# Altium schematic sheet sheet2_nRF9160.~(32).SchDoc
size A3; SheetNumber: 2; SheetTotal: 3
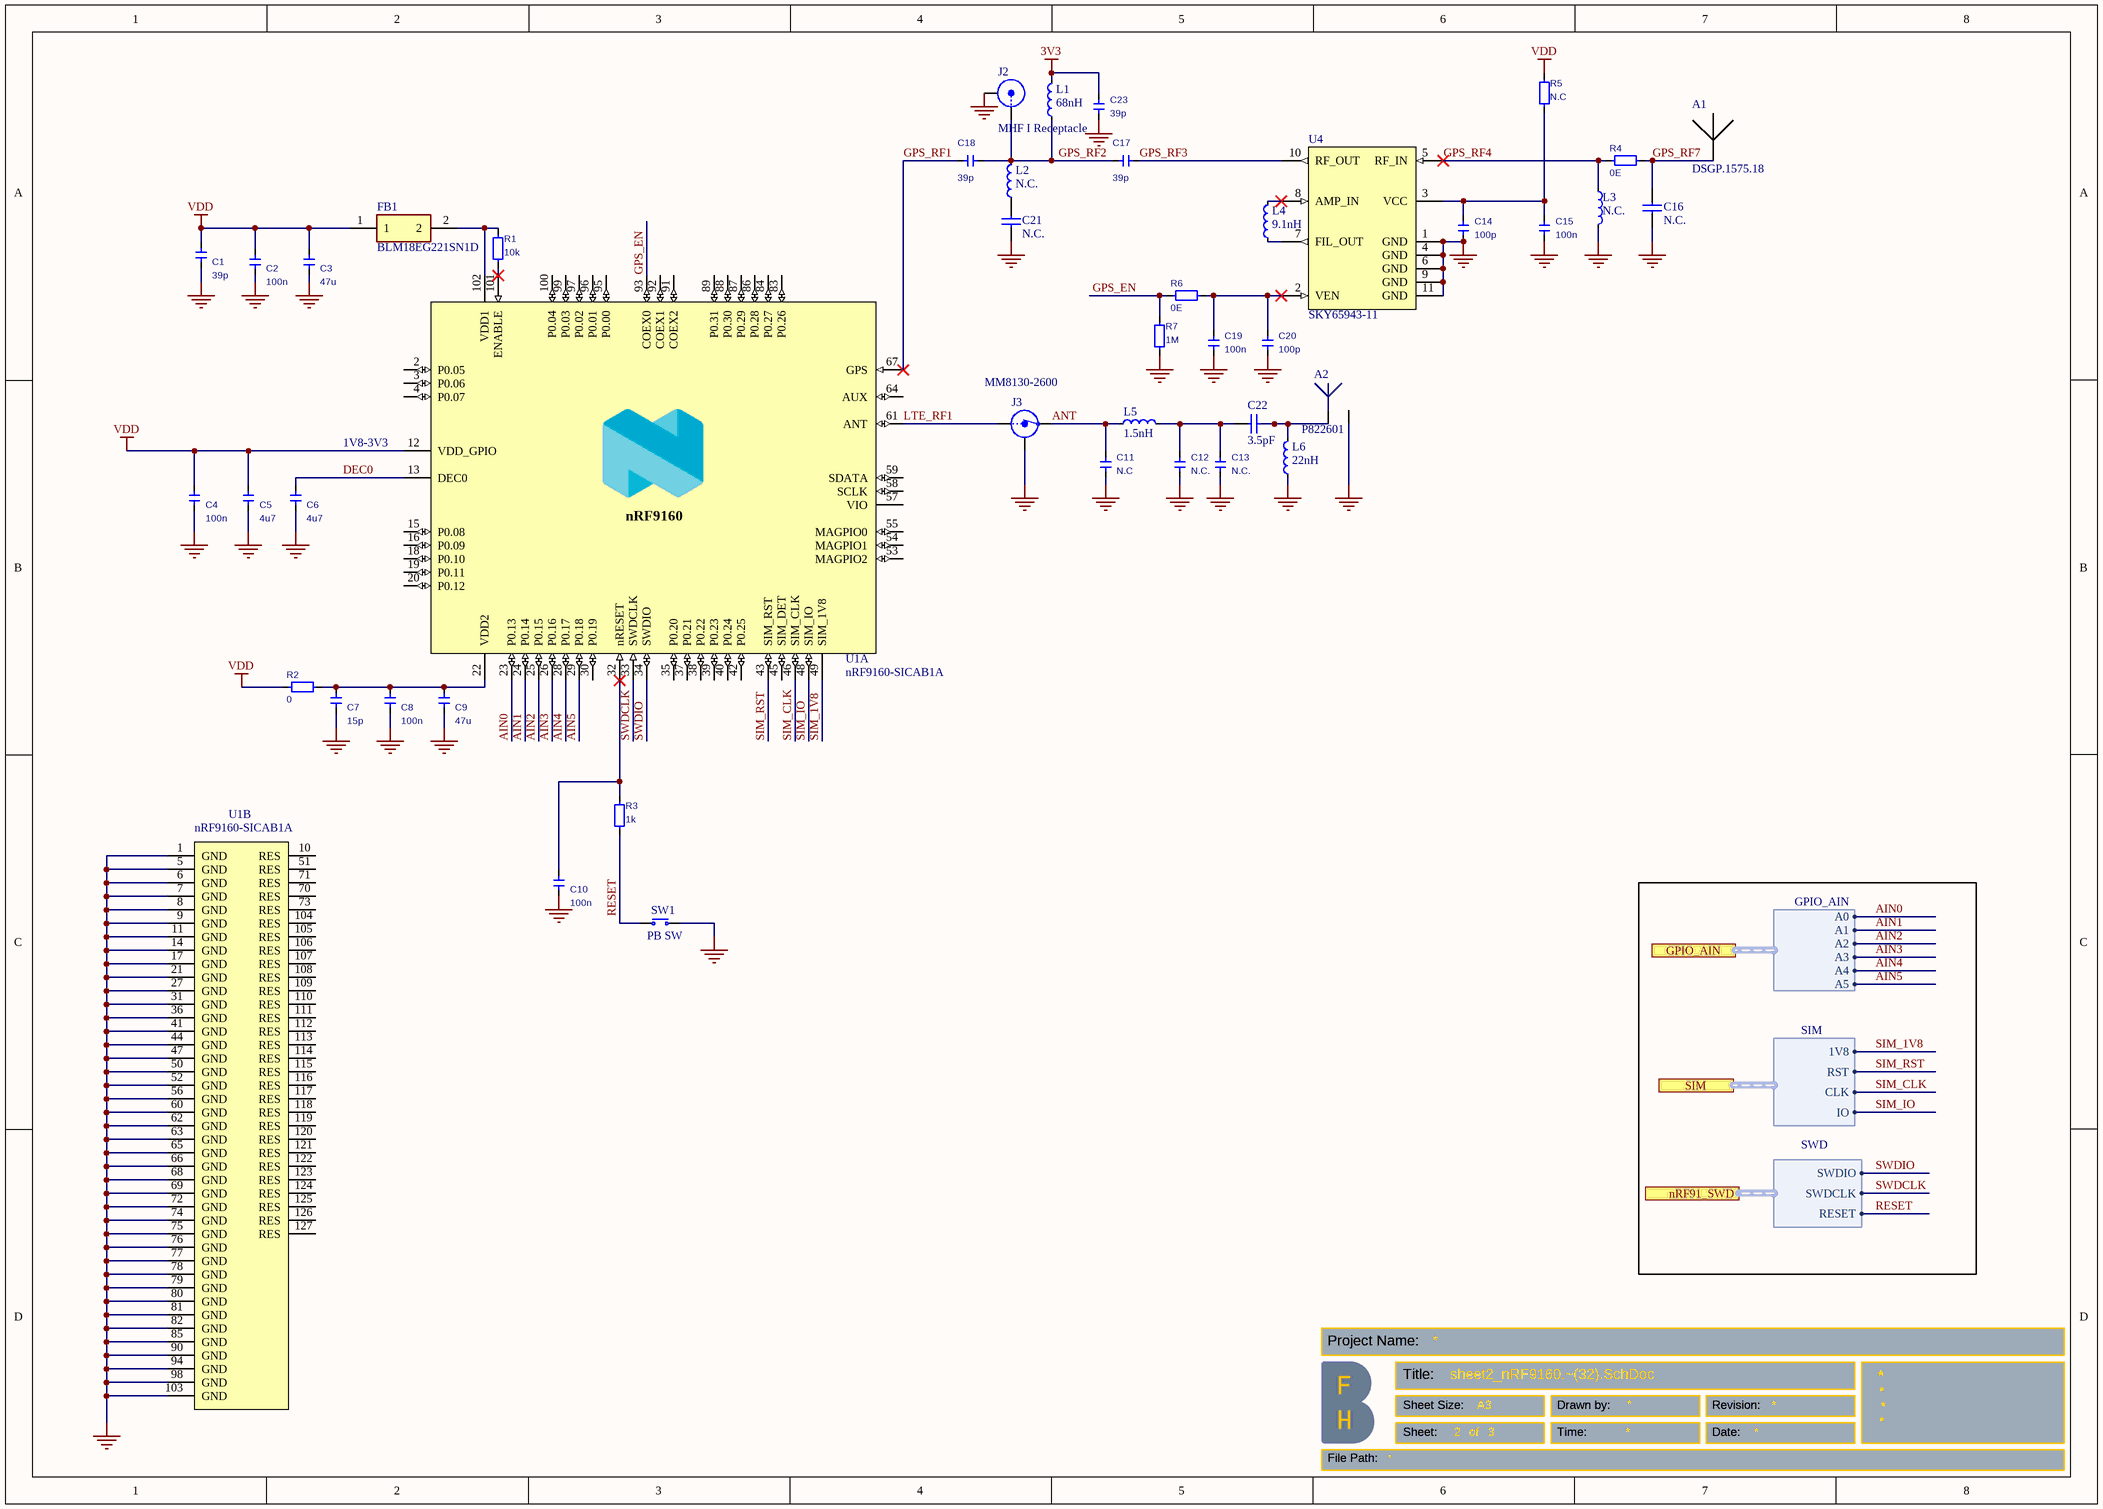
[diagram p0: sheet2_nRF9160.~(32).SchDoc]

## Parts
A1  DSGP.1575.18  [DSGP.1575.18]
A2  P822601  [P822601]
C1  39p  [0603(1608)C]
C2  100n  [0603(1608)C]
C3  47u  [1206(3216)C]
C4  100n  [0603(1608)C]
C5  4u7  [0603(1608)C]
C6  4u7  [0603(1608)C]
C7  15p  [0603(1608)C]
C8  100n  [0603(1608)C]
C9  47u  [1206(3216)C]
C10  100n  [0603(1608)C]
C11  N.C  [0603(1608)C]
C12  N.C.  [0603(1608)C]
C13  N.C.  [0603(1608)C]
C14  100p  [0603(1608)C]
C15  100n  [0603(1608)C]
C16  N.C.  [CAPC1005X04L_NC]
C17  39p  [0603(1608)C]
C18  39p  [0603(1608)C]
C19  100n  [0603(1608)C]
C20  100p  [0603(1608)C]
C21  N.C.  [CAPC0603X03L_C_NC]
C22  3.5pF  [CAPC0603X03L_C]
C23  39p  [0603(1608)C]
FB1  BLM18EG221SN1D  [BLM18SP221SN1B]
J2  MHF I Receptacle  [COAXIAL RF U.FL-R-SMT-1]
J3  MM8130-2600  [COAXIAL-SWF]
L1  68nH  [INDC1005X04L_WW]
L2  N.C.  [INDC1005X04L_NC]
L3  N.C.  [INDC1005X04L_NC]
L4  9.1nH  [INDC1005X04L_WW]
L5  1.5nH  [INDC0603X03L_C]
L6  22nH  [INDC0603X03L_C]
R1  10k  [0603(1608)]
R2  0  [0603(1608)]
R3  1k  [0603(1608)]
R4  0E  [0603(1608)]
R5  N.C  [0603(1608)]
R6  0E  [0603(1608)]
R7  1M  [0603(1608)]
SW1  PB SW  [Switch-PB-6.2x6.3mm-SMD]
U1  nRF9160-SICAB1A  [LGA50P1600X1050X104-161N]  (parts A,B of 2)
U4  SKY65943-11  [SKY65943-11]

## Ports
GPIO_AIN (harness GPIO_AIN, see sheet4_sim_connections[1A]), nRF91_SWD (harness SWD, see sheet4_sim_connections[2B]), SIM (harness SIM, see sheet4_sim_connections[3A])

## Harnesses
GPIO_AIN: A0, A1, A2, A3, A4, A5
SIM: 1V8, RST, CLK, IO
SWD: SWDIO, SWDCLK, RESET

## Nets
3V3: C23.2 L1.1
GND: A1.2(GND) A2.2 C1.2 C2.2 C3.2 C4.2 C5.2 C6.2 C7.2 C8.2 C9.2 C10.2 C11.1 C12.1 C13.1 C14.1 C15.1 C16.2 C19.1 C20.1 C21.1 C23.1 J2.2(Y) J3.2(Shield) L3.2 L6.1 R7.1 SW1.1(N.O) U1.1(GND) U1.5(GND) U1.6(GND) U1.7(GND) U1.8(GND) U1.9(GND) U1.11(GND) U1.14(GND) U1.17(GND) U1.21(GND) U1.27(GND) U1.31(GND) U1.36(GND) U1.41(GND) U1.44(GND) U1.47(GND) U1.50(GND) U1.52(GND) U1.56(GND) U1.60(GND) U1.62(GND) U1.63(GND) U1.65(GND) U1.66(GND) U1.68(GND) U1.69(GND) U1.72(GND) U1.74(GND) U1.75(GND) U1.76(GND) U1.77(GND) U1.78(GND) U1.79(GND) U1.80(GND) U1.81(GND) U1.82(GND) U1.85(GND) U1.90(GND) U1.94(GND) U1.98(GND) U1.103(GND) U4.1(GND) U4.4(GND) U4.6(GND) U4.9(GND) U4.11(GND)
VDD: C1.1 C2.1 C3.1 C4.1 C5.1 FB1.1 R2.1 R5.2 U1.12(VDD_GPIO)
AIN0: U1.23(P0.13) ; port GPIO_AIN.A0
AIN1: U1.24(P0.14) ; port GPIO_AIN.A1
AIN2: U1.25(P0.15) ; port GPIO_AIN.A2
AIN3: U1.26(P0.16) ; port GPIO_AIN.A3
AIN4: U1.28(P0.17) ; port GPIO_AIN.A4
AIN5: U1.29(P0.18) ; port GPIO_AIN.A5
ANT: C11.2 J3.3(OUT) L5.1
DEC0: C6.1 U1.13(DEC0)
GPS_EN: R6.1 R7.2 U1.93(COEX0)
GPS_RF1: C18.2 U1.67(GPS)
GPS_RF2: C17.2 C18.1 J2.1(X) L1.2 L2.1
GPS_RF3: C17.1 U4.10(RF_OUT)
GPS_RF4: L3.1 R4.1 U4.5(RF_IN)
GPS_RF7: A1.1 C16.1 R4.2
LTE_RF1: J3.1(IN) U1.61(ANT)
RESET: R3.1 SW1.2(COM) ; port nRF91_SWD.RESET
SIM_1V8: U1.49(SIM_1V8) ; port SIM.1V8
SIM_CLK: U1.46(SIM_CLK) ; port SIM.CLK
SIM_IO: U1.48(SIM_IO) ; port SIM.IO
SIM_RST: U1.43(SIM_RST) ; port SIM.RST
SWDCLK: U1.33(SWDCLK) ; port nRF91_SWD.SWDCLK
SWDIO: U1.34(SWDIO) ; port nRF91_SWD.SWDIO
NetA2_1: A2.1 C22.2 L6.2
NetC7_1: C7.1 C8.1 C9.1 R2.2 U1.22(VDD2)
NetC10_1: C10.1 R3.2 U1.32(nRESET)
NetC12_2: C12.2 C13.2 C22.1 L5.2
NetC14_2: C14.2 C15.2 R5.1 U4.3(VCC)
NetC19_2: C19.2 C20.2 R6.2 U4.2(VEN)
NetC21_2: C21.2 L2.2
NetFB1_2: FB1.2 R1.1 U1.102(VDD1)
NetL4_1: L4.1 U4.8(AMP_IN)
NetL4_2: L4.2 U4.7(FIL_OUT)
NetR1_2: R1.2 U1.101(ENABLE)

Not connected (* = marked no-connect by the designer): U1 2(P0.05) 3(P0.06) 4(P0.07) 10(RES) 15(P0.08) 16(P0.09) 18(P0.10) 19(P0.11) 20(P0.12) 30(P0.19) 35(P0.20) 37(P0.21) 38(P0.22) 39(P0.23) 40(P0.24) 42(P0.25) 45(SIM_DET) 51(RES) 53(MAGPIO2) 54(MAGPIO1) 55(MAGPIO0) 57(VIO) 58(SCLK) 59(SDATA) 64(AUX) 70(RES) 71(RES) 73(RES) 83(P0.26) 84(P0.27) 86(P0.28) 87(P0.29) 88(P0.30) 89(P0.31) 91(COEX2) 92(COEX1) 95(P0.00) 96(P0.01) 97(P0.02) 99(P0.03) 100(P0.04) 104(RES) 105(RES) 106(RES) 107(RES) 108(RES) 109(RES) 110(RES) 111(RES) 112(RES) 113(RES) 114(RES) 115(RES) 116(RES) 117(RES) 118(RES) 119(RES) 120(RES) 121(RES) 122(RES) 123(RES) 124(RES) 125(RES) 126(RES) 127(RES)

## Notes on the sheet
- 1V8-3V3

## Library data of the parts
A1 = DSGP.1575.18.4.A.02: 18 x 18 mm Low Profile GPS L1 / GALILEO E1 Passive Patch Antenna; Manufacturer: Taoglas; Part number IPS: 00000004435; Note: N.A.; Pad Count: 2
A2 = P822601: ANTENNA PRESTTA OCTABAND LTE; Manufacturer: Ethertronics; Part number IPS: 00000009001; Note: N.A.; Pad Count: 2
C1 = C0603_1_39p_50V: Cer Chip Capacitor / 15p/ +-1%/ 50V; Manufacturer: Murata; Manufacturer P/N: GCM1885C1H390FA16J; Special Value 1: +-1%
C2 C4 C8 C10 C15 C19 = C0603_5_100n_25V: Cer Chip Capacitor / 100n/ +-5%/ 25V; Manufacturer Part Number: CC0603KRX7R8BB104; Manufacturer 1: Yageo; Special Value 1: +-5%; Capacitance: 100nF; Tolerance: 10%; Dielectric: X7R
C3 C9 = C1206_7_47u_6.3V: Cer Chip Capacitor / 47u/ +-10%/ 6.3V; Manufacturer Part Number: CL31A476MQHNNNE; Manufacturer 1: Samsung; Special Value 1: +-20%; Material: Ceramic; Capacitance: 47uF; Tolerance: 20%; Dielectric: X5R
C5 C6 = C0603_6_4u7_25V: Cer Chip Capacitor / 4u7/ +-10%/ 25V; Manufacturer Part Number: CL10A475MA8NQNC; Manufacturer 1: Samsung; Special Value 1: +-10%; Capacitance: 4.7uF; Tolerance: 20%; Dielectric: X5R
C7 = C0603_1_39p_50V: Cer Chip Capacitor / 15p/ +-1%/ 50V; Manufacturer: Murata; Manufacturer P/N: GCM1885C1H390FA16J; Value: 39p; Special Value 1: +-1%
C11-C13 = C0603: Cer Chip Capacitor
C14 C20 = C0603_2_100p_50V: Cer Chip Capacitor / 100p/ +-1%/ 50V; Manufacturer: Murata; Manufacturer P/N: GCM1885C1H101FA16D; Special Value 1: +-1%
C16 = C0402-N.C.: Not mounted; Manufacturer: N.A.; Assembly: Not mounted; Note: Chip Cap; Pad Count: 2
C17 C18 C23 = C0603_1_39p_50V: Cer Chip Capacitor / 39p/ +-1%/ 50V; Manufacturer: Murata; Manufacturer P/N: GCM1885C1H390FA16J; Special Value 1: +-1%
C21 = C0201-N.C.: Not mounted; Manufacturer: N.A.; Assembly: Not mounted; Note: Chip Cap; Pad Count: 2
C22 = C0201-3.5p: Capacitor, NP0, ±0.1pF, 25V; Manufacturer: Murata; Manufacturer Part Number: GJM0335C1H3R5BB01E; Part number IPS: 00000001469; Artikkelnr Noca: N.A.; Pad Count: 2
FB1 = BLM18EG221SN1D: Ferrite Bead; Manufacturer_Name: Murata Electronics
J2 = 20279-001E-03: Ultraminiature Coaxial Connector, 50 Ohm, SMD; Manufacturer: Wellshow; Part number IPS: 00000004436; Note: N.A.; Pad Count: 3
J3 = MM8130-2600: Coaxial Connector with Switch; Manufacturer: Murata; Part number IPS: 00000009955; Note: N.A.; Artikkelnr Noca: 55029011; Pad Count: 3
L1 = L0402-68n-Wirewound-Murata: Inductor, 140mA, ±2%, 1960mΩ, Q=20; Manufacturer: Murata; Manufacturer Part Number: LQW15AN68NG00; Part number IPS: 00000002494; Note: -55°C ~ 125°C; Artikkelnr Noca: N.A.; Pad Count: 2
L2 L3 = L0402-N.C.: Not mounted; Manufacturer: N.A.; Assembly: Not mounted; Pad Count: 2
L4 = L0402-9n1-Wirewound-Murata: Inductor, 540mA, ±2%, 140mΩ, Q=25; Manufacturer: Murata; Manufacturer Part Number: LQW15AN9N1G00; Part number IPS: 00000002497; Note: -55°C ~ 125°C; Artikkelnr Noca: N.A.; Pad Count: 2
L5 = L0201-1n5: Inductor, 650mA, ±0.1nH; Manufacturer: Murata; Manufacturer Part Number: LQP03TQ1N5B02D; Part number IPS: 00000000836; Note: N.A.; Pad Count: 2
L6 = L0201-22n: Chip Inductor; Manufacturer: N.A.; Part number IPS: 00000001478; Note: High frequency chip inductor ±10%; Pad Count: 2
R1 = R0603_4_10k: Chip Resistor / 10k/ 1% / 50V / 100mW / 0603(1608); Manufacturer Part Number: RR0816P-103-D; Manufacturer 1: Susumu; Resistance: 10kR; Tolerance: 0.5%; Power Rating: 63mW; Voltage Rating: 75V; Temperature Coefficient: 25ppm/°C
R2 R4-R6 = R0603_0_0E: Chip Resistor / 0E / 1% / 50V / 100mW / 0603(1608); Manufacturer Part Number: ERJ-3GEY0R00V; Manufacturer 1: Panasonic; Resistance: 0mR; Voltage Rating: 75V; Tolerance: 0%; Temperature Coefficient: 600ppm/°C
R3 = R0603_3_1k: Chip Resistor / 1k/ 1% / 50V / 100mW / 0603(1608); Manufacturer: Panasonic; Manufacturer Part Number: ERA-8AEB102V; Resistance: 1kR; Power Rating: 250mW; Tolerance: 0.1%; Voltage Rating: 150V; Temperature Coefficient: 25ppm/°C
R7 = R0603_6_1M: Chip Resistor / 1M/ 1% / 50V / 100mW / 0603(1608); Manufacturer Part Number: ERJ-8ENF1004V; Resistance: 1MR; Voltage Rating: 200V; Power Rating: 250mW; Temperature Coefficient: 100ppm/°C
SW1 = Switch-PB-6.2x6.3mm-SMD: Tactile Switch, SPNO, SMD, 160gf, 6.2x6.3x2.5mm; Manufacturer: Dailywell; Manufacturer Part Number: TS604VM1-025BR-R; Part number IPS: 00000007812; Note: N.A.; Artikkelnr Noca: 50019106; Pad Count: 4
U1 = nRF9160-SICAB1A: Low power System-in-Package with integrated LTE-M/NB-IoT modem and GPS; Manufacturer: Nordic Semiconductor; Part number IPS: 80000002329; Note: N.A.; Pad Count: 161
U4 = SKY65943-11: GNSS Low-Noise Amplifier Front-End Module with Integrated Pre-Filter and Post-Filter; Manufacturer: Skyworks; Part number IPS: 00000002997; Note: N.A.; Pad Count: 10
